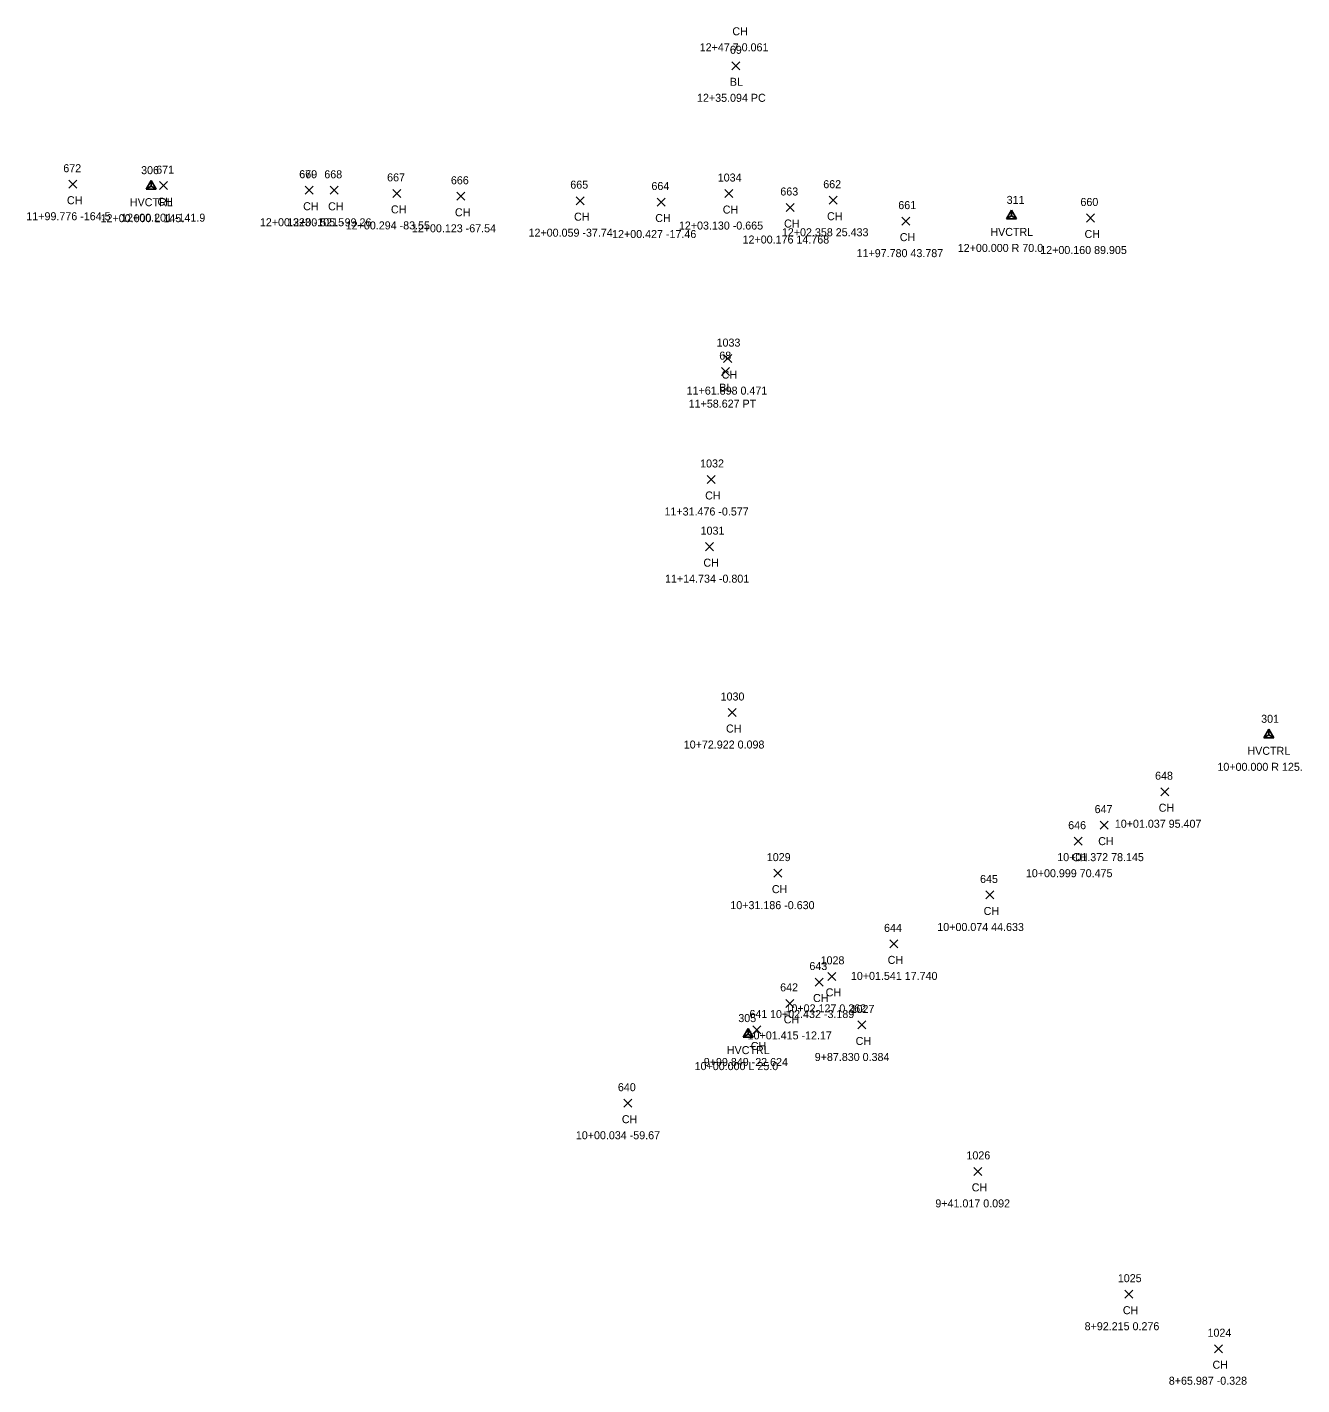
# Model space of a CAD drawing. Extents: x 89316 to 92454, y 84175 to 86051.
# Drawn here: x 90778.3 to 91096.9, y 84564.2 to 84903.5 of the extents above; entities that cross this region are included whole.
import ezdxf

# ---------------------------------------------------------------- set-up
doc = ezdxf.new("R2010")
doc.units = 0
for name, color, linetype in [('C_A', 7, 'Continuous'), ('C_C', 7, 'Continuous'), ('C_I', 7, 'Continuous'), ('C_TIC', 7, 'Continuous'), ('CPSM', 7, 'Continuous'), ('L_A', 7, 'Continuous'), ('L_C', 7, 'Continuous'), ('L_I', 7, 'Continuous'), ('L_TIC', 7, 'Continuous')]:
    doc.layers.add(name, color=color, linetype=linetype)

msp = doc.modelspace()

# ---------------------------------------------------------------- linework, layer by layer
at = {"layer": 'C_TIC'}
for points in [[(90954.47, 84892.82), (90956.47, 84894.82)], [(90956.47, 84892.82), (90954.47, 84894.82)], [(90951.82, 84816.4), (90953.82, 84818.4)], [(90953.82, 84816.4), (90951.82, 84818.4)]]:
    msp.add_lwpolyline(points, dxfattribs=at)
at = {"layer": 'CPSM'}
for p, q in [((90808.07, 84863.02), (90809.32, 84865.19)), ((90808.07, 84863.02), (90809.32, 84863.74)), ((90808.07, 84863.02), (90810.57, 84863.02)), ((90810.57, 84863.02), (90809.32, 84865.19)), ((90809.32, 84863.74), (90809.32, 84865.19)), ((90809.32, 84863.74), (90809.32, 84863.74)), ((90809.32, 84863.74), (90810.57, 84863.02)), ((91023.1, 84855.59), (91024.35, 84857.76)), ((91023.1, 84855.59), (91024.35, 84856.31)), ((91023.1, 84855.59), (91025.6, 84855.59)), ((91025.6, 84855.59), (91024.35, 84857.76)), ((91024.35, 84856.31), (91024.35, 84857.76)), ((91024.35, 84856.31), (91024.35, 84856.31)), ((91024.35, 84856.31), (91025.6, 84855.59)), ((91087.35, 84725.94), (91088.6, 84728.11)), ((91087.35, 84725.94), (91088.6, 84726.66)), ((91089.85, 84725.94), (91088.6, 84728.11)), ((91088.6, 84726.66), (91088.6, 84728.11)), ((91088.6, 84726.66), (91088.6, 84726.66)), ((91088.6, 84726.66), (91089.85, 84725.94)), ((91087.35, 84725.94), (91089.85, 84725.94)), ((90957.25, 84651.15), (90958.5, 84653.32)), ((90959.75, 84651.15), (90958.5, 84653.32)), ((90958.5, 84651.88), (90958.5, 84653.32)), ((90957.25, 84651.15), (90958.5, 84651.88)), ((90957.25, 84651.15), (90959.75, 84651.15)), ((90958.5, 84651.88), (90958.5, 84651.88)), ((90958.5, 84651.88), (90959.75, 84651.15))]:
    msp.add_line(p, q, dxfattribs=at)
at = {"layer": 'L_TIC'}
for points in [[(90788.79, 84863.23), (90790.79, 84865.23)], [(90790.79, 84863.23), (90788.79, 84865.23)], [(90811.43, 84862.87), (90813.43, 84864.87)], [(90813.43, 84862.87), (90811.43, 84864.87)], [(90847.82, 84861.73), (90849.82, 84863.73)], [(90849.82, 84861.73), (90847.82, 84863.73)], [(90847.82, 84861.73), (90849.82, 84863.73)], [(90849.82, 84861.73), (90847.82, 84863.73)], [(90854.06, 84861.71), (90856.06, 84863.71)], [(90856.06, 84861.71), (90854.06, 84863.71)], [(90869.76, 84860.94), (90871.76, 84862.94)], [(90871.76, 84860.94), (90869.76, 84862.94)], [(90952.69, 84860.9), (90954.69, 84862.9)], [(90954.69, 84860.9), (90952.69, 84862.9)], [(90885.75, 84860.22), (90887.75, 84862.22)], [(90887.75, 84860.22), (90885.75, 84862.22)], [(90915.52, 84859.12), (90917.52, 84861.12)], [(90917.52, 84859.12), (90915.52, 84861.12)], [(90935.81, 84858.78), (90937.81, 84860.78)], [(90937.81, 84858.78), (90935.81, 84860.78)], [(90968.01, 84857.41), (90970.01, 84859.41)], [(90970.01, 84857.41), (90968.01, 84859.41)], [(90978.75, 84859.23), (90980.75, 84861.23)], [(90980.75, 84859.23), (90978.75, 84861.23)], [(90996.93, 84854.01), (90998.93, 84856.01)], [(90998.93, 84854.01), (90996.93, 84856.01)], [(91043.11, 84854.79), (91045.11, 84856.79)], [(91045.11, 84854.79), (91043.11, 84856.79)], [(90952.4, 84819.66), (90954.4, 84821.66)], [(90954.4, 84819.66), (90952.4, 84821.66)], [(90948.3, 84789.46), (90950.3, 84791.46)], [(90950.3, 84789.46), (90948.3, 84791.46)], [(90947.85, 84772.67), (90949.85, 84774.67)], [(90949.85, 84772.67), (90947.85, 84774.67)], [(90953.5, 84731.23), (90955.5, 84733.23)], [(90955.5, 84731.23), (90953.5, 84733.23)], [(91061.62, 84711.44), (91063.62, 84713.44)], [(91063.62, 84711.44), (91061.62, 84713.44)], [(91046.51, 84703.09), (91048.51, 84705.09)], [(91048.51, 84703.09), (91046.51, 84705.09)], [(91039.96, 84699.08), (91041.96, 84701.08)], [(91041.96, 84699.08), (91039.96, 84701.08)], [(90964.96, 84691.1), (90966.96, 84693.1)], [(90966.96, 84691.1), (90964.96, 84693.1)], [(91017.88, 84685.64), (91019.88, 84687.64)], [(91019.88, 84685.64), (91017.88, 84687.64)], [(90993.89, 84673.42), (90995.89, 84675.42)], [(90995.89, 84673.42), (90993.89, 84675.42)], [(90975.24, 84663.89), (90977.24, 84665.89)], [(90977.24, 84663.89), (90975.24, 84665.89)], [(90978.4, 84665.31), (90980.4, 84667.31)], [(90980.4, 84665.31), (90978.4, 84667.31)], [(90967.93, 84658.56), (90969.93, 84660.56)], [(90969.93, 84658.56), (90967.93, 84660.56)], [(90959.69, 84651.91), (90961.69, 84653.91)], [(90961.69, 84651.91), (90959.69, 84653.91)], [(90985.89, 84653.16), (90987.89, 84655.16)], [(90987.89, 84653.16), (90985.89, 84655.16)], [(90927.47, 84633.61), (90929.47, 84635.61)], [(90929.47, 84633.61), (90927.47, 84635.61)], [(91014.9, 84616.58), (91016.9, 84618.58)], [(91016.9, 84616.58), (91014.9, 84618.58)], [(91052.67, 84585.89), (91054.67, 84587.89)], [(91054.67, 84585.89), (91052.67, 84587.89)], [(91075.08, 84572.27), (91077.08, 84574.27)], [(91077.08, 84572.27), (91075.08, 84574.27)]]:
    msp.add_lwpolyline(points, dxfattribs=at)

# ---------------------------------------------------------------- texts
at = {"layer": 'C_A'}
for s, p in [('BL', (90953.95, 84888.82)), ('HVCTRL', (90804.01, 84858.74)), ('HVCTRL', (91019.05, 84851.31)), ('BL', (90951.3, 84812.4)), ('HVCTRL', (91083.29, 84721.66)), ('HVCTRL', (90953.19, 84646.88))]:
    msp.add_text(s, height=2, dxfattribs=at).set_placement(p)
at = {"layer": 'C_C'}
for s, p in [('12+35.094 PC', (90945.74, 84884.82)), ('12+00.000 L 145.', (90796.69, 84854.74)), ('12+00.000 R 70.0', (91010.9, 84847.31)), ('11+58.627 PT', (90943.66, 84808.4)), ('10+00.000 R 125.', (91075.79, 84717.66)), ('10+00.000 L 25.0', (90945.14, 84642.88))]:
    msp.add_text(s, height=2, dxfattribs=at).set_placement(p)
at = {"layer": 'C_I'}
for s, p in [('69', (90953.95, 84896.82)), ('306', (90806.82, 84866.74)), ('311', (91023.12, 84859.31)), ('68', (90951.3, 84820.4)), ('301', (91086.72, 84729.66)), ('305', (90956.06, 84654.88))]:
    msp.add_text(s, height=2, dxfattribs=at).set_placement(p)
at = {"layer": 'L_A'}
for p in [(90954.57, 84901.44), (90788.28, 84859.23), (90810.92, 84858.87), (90847.31, 84857.73), (90847.31, 84857.73), (90853.55, 84857.71), (90869.25, 84856.94), (90952.18, 84856.9), (90885.24, 84856.22), (90915.01, 84855.12), (90935.3, 84854.78), (90978.24, 84855.23), (90967.5, 84853.41), (91042.59, 84850.79), (90996.42, 84850.01), (90951.89, 84815.66), (90947.78, 84785.46), (90947.34, 84768.67), (90952.99, 84727.23), (91061.11, 84707.44), (91046, 84699.09), (91039.45, 84695.08), (90964.45, 84687.1), (91017.37, 84681.64), (90993.38, 84669.42), (90977.89, 84661.31), (90974.73, 84659.89), (90967.41, 84654.56), (90959.18, 84647.91), (90985.38, 84649.16), (90926.96, 84629.61), (91014.39, 84612.58), (91052.16, 84581.89), (91074.57, 84568.27)]:
    msp.add_text('CH', height=2, dxfattribs=at).set_placement(p)
at = {"layer": 'L_C'}
for s, p in [('12+47.7 0.061', (90946.41, 84897.44)), ('11+99.776 -164.5', (90778.14, 84855.23)), ('12+00.201 -141.9', (90801.81, 84854.87)), ('12+00.323 -105.5', (90836.5, 84853.73)), ('12+00.323 -105.5', (90836.5, 84853.73)), ('12+00.521 -99.26', (90843.33, 84853.71)), ('12+00.294 -83.55', (90857.96, 84852.94)), ('12+00.123 -67.54', (90874.47, 84852.22)), ('12+00.059 -37.74', (90903.64, 84851.12)), ('12+00.427 -17.46', (90924.52, 84850.78)), ('12+03.130 -0.665', (90941.21, 84852.9)), ('12+02.358 25.433', (90966.95, 84851.23)), ('12+00.176 14.768', (90957.13, 84849.41)), ('12+00.160 89.905', (91031.51, 84846.79)), ('11+97.780 43.787', (90985.62, 84846.01)), ('11+61.898 0.471', (90943.15, 84811.66)), ('11+31.476 -0.577', (90937.61, 84781.46)), ('11+14.734 -0.801', (90937.75, 84764.67)), ('10+72.922 0.098', (90942.43, 84723.23)), ('10+01.037 95.407', (91050.15, 84703.44)), ('10+01.372 78.145', (91035.76, 84695.09)), ('10+00.999 70.475', (91027.92, 84691.08)), ('10+31.186 -0.630', (90954.07, 84683.1)), ('10+00.074 44.633', (91005.79, 84677.64)), ('10+01.541 17.740', (90984.19, 84665.42)), ('10+02.127 0.262', (90967.85, 84657.31)), ('10+02.432 -3.189', (90963.99, 84655.89)), ('10+01.415 -12.17', (90958.39, 84650.56)), ('9+99.849 -22.624', (90947.43, 84643.91)), ('9+87.830 0.384', (90975.16, 84645.16)), ('10+00.034 -59.67', (90915.46, 84625.61)), ('9+41.017 0.092', (91005.3, 84608.58)), ('8+92.215 0.276', (91042.61, 84577.89)), ('8+65.987 -0.328', (91063.64, 84564.27))]:
    msp.add_text(s, height=2, dxfattribs=at).set_placement(p)
at = {"layer": 'L_I'}
for s, p in [('672', (90787.38, 84867.23)), ('671', (90810.59, 84866.87)), ('670', (90846.32, 84865.73)), ('669', (90846.35, 84865.73)), ('668', (90852.6, 84865.71)), ('667', (90868.3, 84864.94)), ('666', (90884.24, 84864.22)), ('1034', (90950.92, 84864.9)), ('665', (90914.07, 84863.12)), ('664', (90934.35, 84862.78)), ('663', (90966.56, 84861.41)), ('662', (90977.29, 84863.23)), ('661', (90996.04, 84858.01)), ('660', (91041.56, 84858.79)), ('1033', (90950.63, 84823.66)), ('1032', (90946.52, 84793.46)), ('1031', (90946.64, 84776.67)), ('1030', (90951.64, 84735.23)), ('648', (91060.21, 84715.44)), ('647', (91045.1, 84707.09)), ('646', (91038.5, 84703.08)), ('1029', (90963.18, 84695.1)), ('645', (91016.47, 84689.64)), ('644', (90992.48, 84677.42)), ('643', (90973.83, 84667.89)), ('1028', (90976.63, 84669.31)), ('642', (90966.52, 84662.56)), ('1027', (90984.12, 84657.16)), ('641', (90958.85, 84655.91)), ('640', (90925.97, 84637.61)), ('1026', (91013.07, 84620.58)), ('1025', (91050.9, 84589.89)), ('1024', (91073.31, 84576.27))]:
    msp.add_text(s, height=2, dxfattribs=at).set_placement(p)

doc.saveas('drawing.dxf')
